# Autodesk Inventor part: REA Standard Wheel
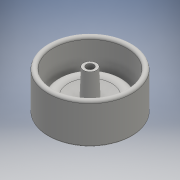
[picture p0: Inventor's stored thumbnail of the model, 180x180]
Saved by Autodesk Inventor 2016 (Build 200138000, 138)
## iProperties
Created: 2015-05
Part Number: REA Standard Wheel
Material: Generic
Document SubType Name: Modeling
Designer: Brett
Density: 1 g/cm^3
Appearance: Default
Author: Brett
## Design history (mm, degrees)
sketch "Sketch2"
  geometry: L1 (16.5, 10.7)-(16.5, -5); L2 (11.5, -5)-(10.8, -1.029); L3 (0.1, -4.427)-(0, -4.427); L4 (16.5, 10.7)-(0, 10.7); L5 (0, -4.427)-(0, 10.7); A1 r 11 centre (14, 5.712) between (11.5, -5) and (16.5, -5); A2 r 15.413 centre (-0.015, 10.986) between (0.1, -4.427) and (9.924, -0.794); A3 r 0.5 centre (10.307, -1.116) between (10.8, -1.029) and (9.924, -0.794); 1 further point
  constraints: 10 end point, 6 point on circle, 3 centre point, 2 horizontal, 1 tangent, 1 vertical
  dimensions: "d3" = 11 radius of A1; "d5" = 170 deg angle of L2 L1; "d6" = 0.1 horizontal distance of L3.start point (0, 0); "d9" = 15.413 radius of A2; "d11" = 0.5 radius of A3; "d12" = 15.7 distance from line of L4 L1.end; "d14" = 16.5 horizontal distance of point (0, 0) L1.end; "d15" = 11.5 horizontal distance of point (0, 0) L2.start
revolve "Revolution1" sketch "Sketch2" stored, may be unused: angle "d16" = 90 deg
shell "Shell1" dims "d17" = 2
workplane "Work Plane1"
sketch "Sketch3"
  geometry: C1 r 3 at (0, 0); 1 further point
  constraints: 1 centre point, 1 coincident
  dimensions: "d19" = 6 diameter of C1
extrude "Extrusion1" join sketch "Sketch3" stored distance "d20" = 10; taper "d21" = 0 deg
feature "FaceDraft1" dims angle "d22" = 2 deg
hole "Hole1" diameter "d45" = 3; stored, may be unused: countersink angle "d49" = 90 deg, drill point angle "d51" = 0 deg; dims "d43" = 10, "d44" = 10, "d46" = 6, "d47" = 4, "d48" = 2, "d50" = 11.5
workplane "Work Plane2"
feature "OffsetSrf1" dims "d32" = 0.75, "d33" = 0.75
sketch "Sketch4"
  geometry: L1 (-0.462, 2.309)-(-2.829, 8.023); L2 (0.462, 2.309)-(2.829, 8.023); L3 (0, 2.307)-(0, 0); A1 r 9.33 centre (0, 0) between (2.323, 9.036) and (-2.323, 9.036); A2 r 0.75 centre (2.136, 8.31) between (2.829, 8.023) and (2.323, 9.036); A3 r 0.75 centre (-2.136, 8.31) between (-2.323, 9.036) and (-2.829, 8.023); A4 r 0.5 centre (0, 2.5) between (-0.462, 2.309) and (0.462, 2.309); 3 further points
  constraints: 10 point on circle, 6 end point, 6 tangent, 4 centre point, 2 point on line, 1 coincident, 1 equal radius, 1 vertical
  dimensions: "d23" = 18.66 diameter of A1; "d26" = 45 deg angle of L1 L2; "d27" = 22.5 deg angle of L3 L2; "d28" = 0.75 radius of A2; "d29" = 0.5 radius of A4; "d30" = 2.5 distance of point (0, 0) A4.centre
extrude "Extrusion2" cut sketch "Sketch4" stored distance "d34" = 3.25; taper "d35" = 0 deg
workaxis "Work Axis1"
pattern_circular "Circular Pattern1" dims angle "d37" = 360 deg
feature "FaceDraft3" dims angle "d52" = 2.5 deg
fillet "Fillet1" dims "d53" = 0.45, "d54" = 0.5, "d55" = 1
body "Solid1"
body "Srf2"
other parameters: "d18" = 0, "d31" = -4.5
